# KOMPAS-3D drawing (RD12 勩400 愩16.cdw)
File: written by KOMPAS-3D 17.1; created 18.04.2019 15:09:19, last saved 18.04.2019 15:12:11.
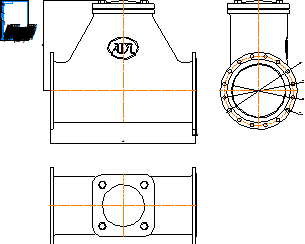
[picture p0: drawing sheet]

Sheet 1: A4, portrait

Title block, sheet 1: name: RD12 Ду400 Ру16; material: Внимание! Данный продукт является объектом авторского права ООО «Торговый Дом АДЛ». / Запрещается изменение, копирование, распространение / (в том числе путем копирования на другие сайты и ресурсы в Интернете) / или любое иное использование информации и объектов без предварительного / согласия правообладателя (ООО «Торговый Дом АДЛ»).; mass: 1915,64; sheets: 1; organisation: ООО "Торговый дом АДЛ"; sheet format: A4

Views: Вид 1, Проекционный вид 2, Проекционный вид 3
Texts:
  user
Dimensions and other numbers on the sheet: 24; 4; 1092; 680; 525; 580; 400; 28; 16 отв.; 1:1; 1; 1915,64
